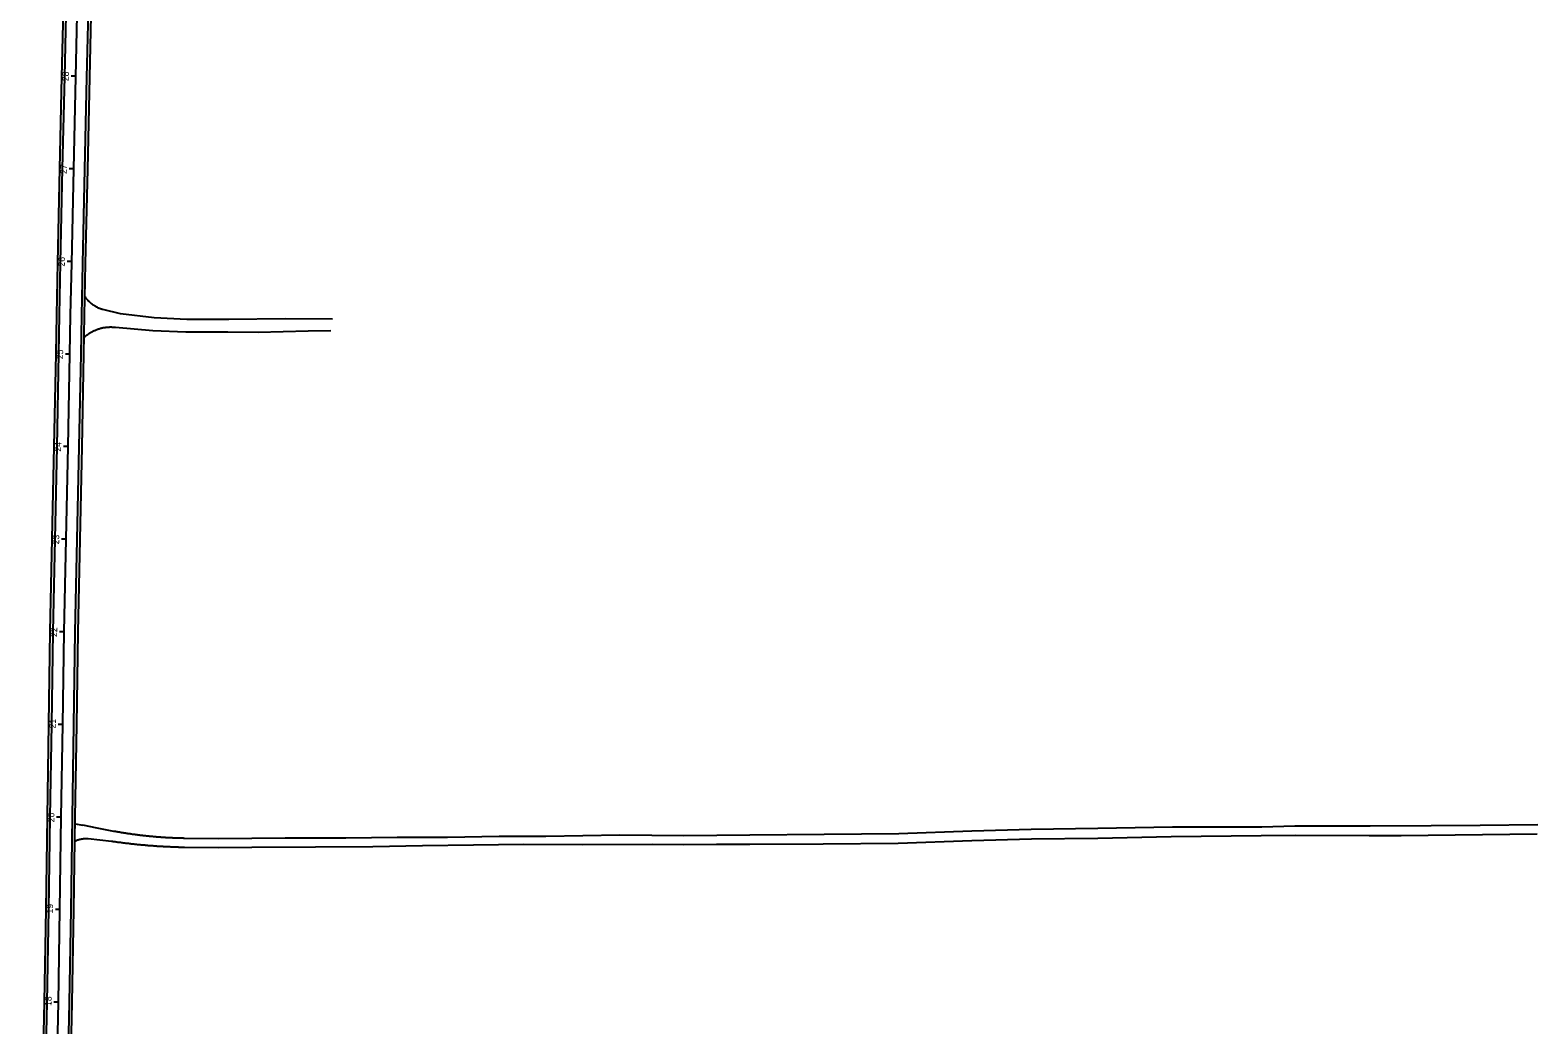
# Model space of a CAD drawing. Extents: x 2318076 to 2324211, y 613525 to 629939.
# Drawn here: x 2318871 to 2320499, y 616711 to 617785 of the extents above; entities that cross this region are included whole.
import ezdxf

# ---------------------------------------------------------------- set-up
doc = ezdxf.new("R2010")
doc.units = 0
for name, color, linetype in [('GE_P_CL_50', 7, 'Continuous'), ('PV_P_EOP', 7, 'Continuous'), ('PV_P_Shoulder', 7, 'Continuous'), ('PV_X_Driveway', 7, 'Continuous')]:
    doc.layers.add(name, color=color, linetype=linetype)

msp = doc.modelspace()

# ---------------------------------------------------------------- linework, layer by layer
at = {"layer": 'GE_P_CL_50'}
for p, q in [((2318920.2, 617735.2), (2318915.2, 617735.3)), ((2318918, 617635.2), (2318913, 617635.3)), ((2318915.9, 617535.2), (2318910.9, 617535.3)), ((2318913.9, 617435.2), (2318909, 617435.3)), ((2318911.9, 617335.3), (2318906.9, 617335.4)), ((2318909.8, 617235.3), (2318904.8, 617235.4)), ((2318907.6, 617135.3), (2318902.6, 617135.4)), ((2318906, 617035.3), (2318901, 617035.4)), ((2318904.5, 616935.3), (2318899.5, 616935.4)), ((2318903.1, 616835.4), (2318898.1, 616835.4)), ((2318901.4, 616735.4), (2318896.4, 616735.5))]:
    msp.add_line(p, q, dxfattribs=at)
msp.add_lwpolyline([(2318885.9, 615635.5), (2318886.2, 615735.5), (2318887.3, 615835.5), (2318888.6, 615935.5), (2318890, 616035.5), (2318891.3, 616134.6), (2318892.9, 616235.4), (2318894.8, 616335.4), (2318896.2, 616435.4), (2318897.2, 616535.4), (2318899.2, 616635.4), (2318901.4, 616735.4), (2318903.1, 616835.4), (2318904.5, 616935.3), (2318906.2, 617035.3), (2318907.6, 617135.3), (2318909.8, 617235.3), (2318911.9, 617335.3), (2318913.9, 617435.2), (2318914.6, 617477.3), (2318915.8, 617533.4), (2318918, 617635.2), (2318920.2, 617734.2), (2318922.5, 617835.2)], dxfattribs=at)
at = {"layer": 'PV_P_EOP'}
for points in [[(2318873.9, 615635.6), (2318874.2, 615735.6), (2318875.3, 615835.6), (2318876.6, 615935.6), (2318878, 616035.6), (2318879.3, 616134.8), (2318880.9, 616235.7), (2318882.8, 616335.6), (2318884.2, 616435.6), (2318885.2, 616535.6), (2318887.2, 616635.6), (2318889.4, 616735.6), (2318891.1, 616835.5), (2318892.5, 616935.5), (2318894.2, 617035.5), (2318895.6, 617135.5), (2318897.8, 617235.5), (2318899.9, 617335.5), (2318902, 617435.5), (2318902.6, 617477.5), (2318903.8, 617533.7), (2318906, 617635.5), (2318908.2, 617734.5), (2318910.5, 617835.4)], [(2318897.9, 615635.4), (2318898.2, 615735.4), (2318899.3, 615835.3), (2318900.6, 615935.3), (2318902, 616035.3), (2318903.3, 616134.4), (2318904.8, 616235.2), (2318906.8, 616335.2), (2318908.2, 616435.3), (2318909.2, 616535.2), (2318911.2, 616635.1), (2318913.4, 616735.1), (2318915.1, 616835.2), (2318916.5, 616935.2), (2318918.2, 617035.1), (2318919.6, 617135.1), (2318921.8, 617235), (2318923.9, 617335), (2318925.9, 617435), (2318926.6, 617477), (2318927.8, 617533.2), (2318930, 617634.9), (2318932.2, 617733.9), (2318934.5, 617834.9)]]:
    msp.add_lwpolyline(points, dxfattribs=at)
at = {"layer": 'PV_P_Shoulder'}
for points in [[(2318870.9, 615635.6), (2318871.2, 615735.6), (2318872.3, 615835.7), (2318873.6, 615935.7), (2318875, 616035.7), (2318876.3, 616134.8), (2318877.9, 616235.7), (2318879.8, 616335.7), (2318881.2, 616435.6), (2318882.2, 616535.6), (2318884.2, 616635.7), (2318886.4, 616735.7), (2318888.1, 616835.6), (2318889.5, 616935.6), (2318891.2, 617035.6), (2318892.6, 617135.6), (2318894.8, 617235.6), (2318896.9, 617335.6), (2318899, 617435.5), (2318899.6, 617477.6), (2318900.8, 617533.7), (2318903, 617635.5), (2318905.2, 617734.5), (2318907.5, 617835.5)], [(2318900.9, 615635.4), (2318901.2, 615735.4), (2318902.3, 615835.3), (2318903.6, 615935.3), (2318905, 616035.3), (2318906.3, 616134.4), (2318907.8, 616235.2), (2318909.8, 616335.2), (2318911.2, 616435.2), (2318912.2, 616535.2), (2318914.2, 616635.1), (2318916.4, 616735.1), (2318918.1, 616835.1), (2318919.5, 616935.1), (2318921.2, 617035.1), (2318922.6, 617135), (2318924.8, 617235), (2318926.9, 617335), (2318928.9, 617435), (2318929.6, 617477), (2318930.8, 617533.1), (2318933, 617634.9), (2318935.2, 617733.9), (2318937.5, 617834.8)]]:
    msp.add_lwpolyline(points, dxfattribs=at)
at = {"layer": 'PV_X_Driveway'}
for p, q in [((2318919.4, 616928.2), (2318927.9, 616926.7)), ((2318933.5, 616912.1), (2318958.8, 616909.4))]:
    msp.add_line(p, q, dxfattribs=at)
for points in [[(2318949.3, 617483.3), (2318948.7, 617483.4), (2318948.2, 617483.6), (2318947.6, 617483.8), (2318947.1, 617484), (2318946.6, 617484.2), (2318946.1, 617484.4), (2318945.5, 617484.6), (2318945, 617484.8), (2318944.5, 617485), (2318944, 617485.3), (2318943.5, 617485.5), (2318943, 617485.8), (2318942.5, 617486), (2318942, 617486.3), (2318941.5, 617486.6), (2318941, 617486.9), (2318940.5, 617487.2), (2318940.1, 617487.5), (2318939.6, 617487.8), (2318939.1, 617488.1), (2318938.7, 617488.4), (2318938.2, 617488.8), (2318937.8, 617489.1), (2318937.3, 617489.5), (2318936.9, 617489.8), (2318936.5, 617490.2), (2318936, 617490.6), (2318935.6, 617490.9), (2318935.2, 617491.3), (2318934.8, 617491.7), (2318934.4, 617492.1), (2318934, 617492.5), (2318933.7, 617493), (2318933.3, 617493.4), (2318932.9, 617493.8), (2318932.6, 617494.2), (2318932.2, 617494.7), (2318931.9, 617495.1), (2318931.5, 617495.6), (2318931.2, 617496), (2318930.9, 617496.5), (2318930.6, 617497), (2318930.3, 617497.5), (2318930.1, 617497.8)], [(2319197.3, 617472.8), (2319146.1, 617473.3), (2319085.5, 617472.7), (2319039.9, 617472.6), (2319004.9, 617474.5), (2318968.6, 617478.7), (2318949.3, 617483.3)], [(2318929.2, 617453.4), (2318929.7, 617453.8), (2318930.2, 617454.3), (2318930.8, 617454.7), (2318931.4, 617455.2), (2318931.9, 617455.6), (2318932.5, 617456.1), (2318933.1, 617456.5), (2318933.7, 617456.9), (2318934.3, 617457.4), (2318934.9, 617457.8), (2318935.5, 617458.2), (2318936.2, 617458.5), (2318936.8, 617458.9), (2318937.4, 617459.3), (2318938.1, 617459.6), (2318938.7, 617460), (2318939.4, 617460.3), (2318940.1, 617460.6), (2318940.7, 617460.9), (2318941.4, 617461.2), (2318942.1, 617461.5), (2318942.8, 617461.7), (2318943.5, 617462), (2318944.1, 617462.2), (2318944.8, 617462.5), (2318945.5, 617462.7), (2318946.2, 617462.9), (2318947, 617463.1), (2318947.7, 617463.3), (2318948.4, 617463.5), (2318949.1, 617463.6), (2318949.8, 617463.8), (2318950.5, 617463.9), (2318951.3, 617464), (2318952, 617464.1), (2318952.7, 617464.2), (2318953.4, 617464.3), (2318954.2, 617464.4), (2318954.9, 617464.4), (2318955.6, 617464.5), (2318956.4, 617464.5), (2318957.1, 617464.6), (2318957.8, 617464.6), (2318958.6, 617464.6), (2318959.3, 617464.5), (2318960, 617464.5), (2318960.8, 617464.5), (2318961.5, 617464.4), (2318962.2, 617464.4), (2318963, 617464.3)], [(2318963, 617464.3), (2319003.4, 617460.7), (2319039, 617459.3), (2319084.3, 617459.2), (2319117, 617458.8), (2319171.2, 617460.5), (2319195.6, 617460.8)], [(2318919.1, 616909.4), (2318920.1, 616909.8), (2318920.5, 616910), (2318921, 616910.2), (2318921.4, 616910.4), (2318921.9, 616910.6), (2318922.4, 616910.7), (2318922.8, 616910.9), (2318923.3, 616911), (2318923.8, 616911.2), (2318924.3, 616911.3), (2318924.7, 616911.4), (2318925.2, 616911.5), (2318925.7, 616911.6), (2318926.2, 616911.7), (2318926.7, 616911.8), (2318927.2, 616911.9), (2318927.6, 616912), (2318928.1, 616912), (2318928.6, 616912.1), (2318929.1, 616912.1), (2318929.6, 616912.2), (2318930.1, 616912.2), (2318930.6, 616912.2), (2318931.1, 616912.2), (2318931.6, 616912.2), (2318932.1, 616912.2), (2318932.6, 616912.2), (2318933.1, 616912.2), (2318933.5, 616912.1)], [(2318961.4, 616919.9), (2318943.4, 616923.5), (2318927.9, 616926.7)], [(2319037.6, 616912.3), (2319036.8, 616912.3), (2319036, 616912.4), (2319035.1, 616912.4), (2319034.3, 616912.4), (2319033.4, 616912.4), (2319032.6, 616912.4), (2319031.7, 616912.5), (2319030.9, 616912.5), (2319030.1, 616912.5), (2319029.2, 616912.5), (2319028.4, 616912.6), (2319027.5, 616912.6), (2319026.7, 616912.6), (2319025.8, 616912.7), (2319025, 616912.7), (2319024.2, 616912.8), (2319023.3, 616912.8), (2319022.5, 616912.8), (2319021.6, 616912.9), (2319020.8, 616912.9), (2319020, 616913), (2319019.1, 616913), (2319018.3, 616913.1), (2319017.4, 616913.1), (2319016.6, 616913.2), (2319015.7, 616913.2), (2319014.9, 616913.3), (2319014.1, 616913.3), (2319013.2, 616913.4), (2319012.4, 616913.4), (2319011.5, 616913.5), (2319010.7, 616913.6), (2319009.9, 616913.6), (2319009, 616913.7), (2319008.2, 616913.8), (2319007.3, 616913.8), (2319006.5, 616913.9), (2319005.7, 616914), (2319004.8, 616914), (2319004, 616914.1), (2319003.1, 616914.2), (2319002.3, 616914.3), (2319001.5, 616914.4), (2319000.6, 616914.4), (2318999.8, 616914.5), (2318999, 616914.6), (2318998.1, 616914.7), (2318997.3, 616914.8), (2318996.4, 616914.9), (2318995.6, 616915), (2318994.8, 616915), (2318993.9, 616915.1), (2318993.1, 616915.2), (2318992.3, 616915.3), (2318991.4, 616915.4), (2318990.6, 616915.5), (2318989.7, 616915.6), (2318988.9, 616915.7), (2318988.1, 616915.8), (2318987.2, 616915.9), (2318986.4, 616916), (2318985.6, 616916.1), (2318984.7, 616916.3), (2318983.9, 616916.4), (2318983.1, 616916.5), (2318982.2, 616916.6), (2318981.4, 616916.7), (2318980.5, 616916.8), (2318979.7, 616916.9), (2318978.9, 616917.1), (2318978, 616917.2), (2318977.2, 616917.3), (2318976.4, 616917.4), (2318975.5, 616917.6), (2318974.7, 616917.7), (2318973.9, 616917.8), (2318973, 616917.9), (2318972.2, 616918.1), (2318971.4, 616918.2), (2318970.6, 616918.3), (2318969.7, 616918.5), (2318968.9, 616918.6), (2318968.1, 616918.8), (2318967.2, 616918.9), (2318966.4, 616919), (2318965.6, 616919.2), (2318964.7, 616919.3), (2318963.9, 616919.5), (2318963.1, 616919.6), (2318962.2, 616919.8), (2318961.4, 616919.9)], [(2319037.4, 616902.9), (2319074.8, 616902.4), (2319110.2, 616902.8), (2319179.1, 616903.3), (2319241.1, 616903.4), (2319294.5, 616904.6), (2319349.6, 616905.4), (2319403.7, 616906.1), (2319467.6, 616905.9), (2319543.4, 616906.1), (2319576.5, 616905.9), (2319611.9, 616906.2), (2319647.9, 616906.1), (2319727.2, 616906.5), (2319808.1, 616907.3), (2319887.6, 616910.1), (2319952.1, 616911.8), (2320023.9, 616912.5), (2320103.1, 616914.4), (2320200, 616915.3), (2320237, 616915.9), (2320316.8, 616915.5), (2320351.2, 616915.6), (2320409.6, 616916.1), (2320498.1, 616917.3)], [(2320498.9, 616927.1), (2320436.5, 616926.2), (2320383.8, 616925.9), (2320318, 616925.4), (2320236.6, 616925.5), (2320200.9, 616924.5), (2320104.4, 616924.5), (2320023.7, 616923), (2319951.7, 616921.9), (2319887.6, 616920), (2319809, 616917.2), (2319728.2, 616916.4), (2319647.9, 616915.7), (2319576.6, 616915.1), (2319507.6, 616915.7), (2319427.6, 616914.4), (2319377.5, 616914.4), (2319321.6, 616913.3), (2319267.2, 616913.2), (2319211.7, 616912.6), (2319146.1, 616912.4), (2319074.4, 616912), (2319037.6, 616912.3)], [(2318958.8, 616909.4), (2318959.8, 616909.3), (2318960.7, 616909.1), (2318961.7, 616909), (2318962.6, 616908.9), (2318963.6, 616908.7), (2318964.6, 616908.6), (2318965.5, 616908.4), (2318966.5, 616908.3), (2318967.5, 616908.2), (2318968.4, 616908.1), (2318969.4, 616907.9), (2318970.4, 616907.8), (2318971.3, 616907.7), (2318972.3, 616907.6), (2318973.3, 616907.4), (2318974.2, 616907.3), (2318975.2, 616907.2), (2318976.2, 616907.1), (2318977.1, 616907), (2318978.1, 616906.9), (2318979.1, 616906.7), (2318980, 616906.6), (2318981, 616906.5), (2318982, 616906.4), (2318983, 616906.3), (2318983.9, 616906.2), (2318984.9, 616906.1), (2318985.9, 616906), (2318986.8, 616905.9), (2318987.8, 616905.8), (2318988.8, 616905.7), (2318989.7, 616905.6), (2318990.7, 616905.5), (2318991.7, 616905.4), (2318992.7, 616905.3), (2318993.6, 616905.3), (2318994.6, 616905.2), (2318995.6, 616905.1), (2318996.5, 616905), (2318997.5, 616904.9), (2318998.5, 616904.8), (2318999.5, 616904.8), (2319000.4, 616904.7), (2319001.4, 616904.6), (2319002.4, 616904.5), (2319003.3, 616904.5), (2319004.3, 616904.4), (2319005.3, 616904.3), (2319006.3, 616904.2), (2319007.2, 616904.2), (2319008.2, 616904.1), (2319009.2, 616904.1), (2319010.2, 616904), (2319011.1, 616903.9), (2319012.1, 616903.9), (2319013.1, 616903.8), (2319014, 616903.8), (2319015, 616903.7), (2319016, 616903.7), (2319017, 616903.6), (2319017.9, 616903.6), (2319018.9, 616903.5), (2319019.9, 616903.5), (2319020.9, 616903.4), (2319021.8, 616903.4), (2319022.8, 616903.3), (2319023.8, 616903.3), (2319024.8, 616903.3), (2319025.7, 616903.2), (2319026.7, 616903.2), (2319027.7, 616903.2), (2319028.7, 616903.1), (2319029.6, 616903.1), (2319030.6, 616903.1), (2319031.6, 616903), (2319032.6, 616903), (2319033.5, 616903), (2319034.5, 616903), (2319035.5, 616903), (2319036.5, 616902.9), (2319037.4, 616902.9)]]:
    msp.add_lwpolyline(points, dxfattribs=at)

# ---------------------------------------------------------------- texts
at = {"layer": 'GE_P_CL_50'}
for s, rotation, p in [('28', 88.5144, (2318912.5, 617729.9)), ('27', 88.608, (2318910.4, 617629.6)), ('26', 88.8343, (2318908.3, 617529.7)), ('25', 89.0866, (2318906.4, 617429.7)), ('24', 88.4011, (2318904.2, 617329.9)), ('23', 89.0975, (2318902.2, 617229.7)), ('22', 89.3393, (2318900, 617129.8)), ('21', 88.8736, (2318898.5, 617031)), ('20', 89.348, (2318897, 616929.7)), ('19', 89.2487, (2318895.5, 616831.2)), ('18', 88.8336, (2318893.9, 616731.3))]:
    msp.add_text(s, height=7, rotation=rotation, dxfattribs=at).set_placement(p)

doc.saveas('drawing.dxf')
